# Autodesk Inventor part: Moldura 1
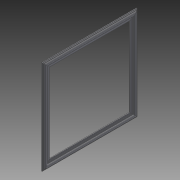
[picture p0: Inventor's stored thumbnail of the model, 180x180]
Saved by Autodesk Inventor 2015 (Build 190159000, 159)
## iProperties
Created: 2015-04
Part Number: Moldura 1
Material: Generic
Document SubType Name: Modeling
Designer: suporte
Density: 1 g/cm^3
Appearance: Default
Author: suporte
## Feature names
1. Sweep1
## Parameters: d2 = 85 mm, d3 = 8 mm, d4 = 5 mm, d5 = 25 mm, d7 = 35 mm, d8 = 5 mm, d9 = 7 mm, d10 = 23 mm, d11 = 0, d12 = 0
